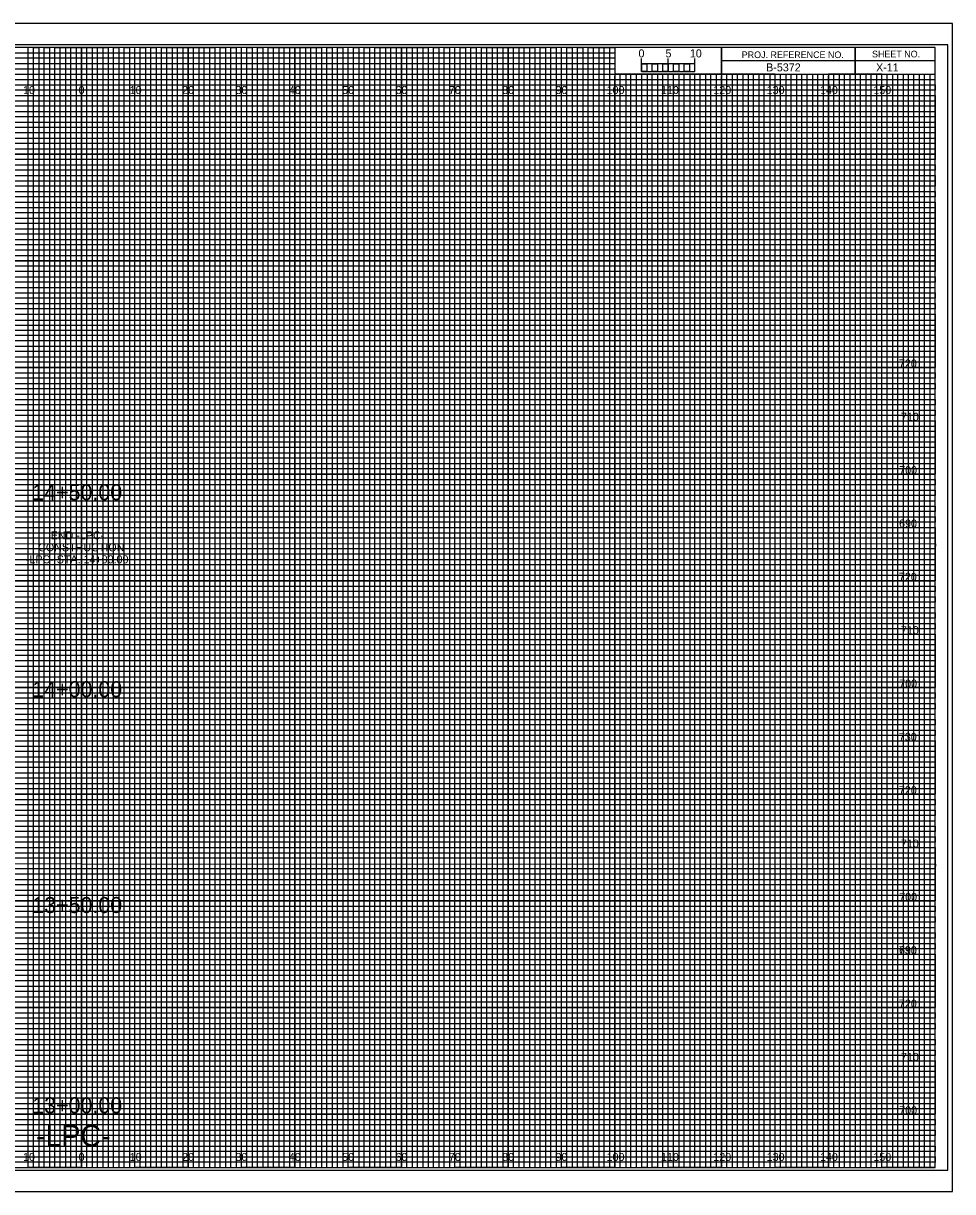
# Model space of a CAD drawing. Extents: x -397 to 323, y -4 to 654.
# Drawn here: x 149.1 to 323.3, y 435.5 to 654.5 of the extents above; entities that cross this region are included whole.
import ezdxf

# ---------------------------------------------------------------- set-up
doc = ezdxf.new("R2010")
doc.units = 0
for name, color, linetype in [('Default', 7, 'Continuous'), ('Exist XS Center Line Elevation Label', 7, 'Continuous'), ('Prop XS Alignment Label', 7, 'Continuous'), ('Prop XS Bar Scale Labels', 7, 'Continuous'), ('Prop XS Elevation Labels', 7, 'Continuous'), ('Prop XS Offset Labels', 7, 'Continuous'), ('Prop XS Project Number', 7, 'Continuous'), ('Prop XS Sheet Number', 7, 'Continuous'), ('Prop XS Station Labels', 7, 'Continuous'), ('Sheet Cross Section CELL', 7, 'Continuous'), ('Sheet Cross Section Grid Major CELL', 7, 'Continuous'), ('Sheet Cross Section Grid Middle CELL', 7, 'Continuous'), ('Sheet Cross Section Grid Minor 1 CELL', 7, 'Continuous'), ('Sheet Cross Section Grid Minor 2 CELL', 7, 'Continuous'), ('Sheet Cross Section Scale CELL', 7, 'Continuous'), ('Sheet Cutting Line CELL', 7, 'Continuous'), ('Sheet DOT Grid CELL', 7, 'Continuous'), ('Sheet Plot Border Inside CELL', 7, 'Continuous'), ('Sheet Plot Border Outside CELL', 7, 'Continuous')]:
    doc.layers.add(name, color=color, linetype=linetype)

msp = doc.modelspace()

# ---------------------------------------------------------------- linework, layer by layer
at = {"layer": 'Default'}
msp.add_lwpolyline([(-13.4, 435.5), (323.3, 435.5), (323.3, 654.5), (-13.4, 654.5)], close=True, dxfattribs=at)
at = {"layer": 'Sheet Cross Section CELL'}
for p, q in [((305, 650), (305, 645)), ((305, 645), (305, 650)), ((280, 647.5), (280, 645)), ((320, 647.49), (280, 647.49)), ((280, 645), (320, 645))]:
    msp.add_line(p, q, dxfattribs=at)
for points in [[(320, 650), (0, 650), (0, 440), (320, 440)], [(280, 650), (260, 650), (260, 645.03), (280, 645.03)], [(320, 650), (280, 650), (280, 645), (320, 645)]]:
    msp.add_lwpolyline(points, close=True, dxfattribs=at)
at = {"layer": 'Sheet Cross Section Grid Major CELL'}
for p, q in [((150, 650), (140, 650)), ((150, 440), (150, 650)), ((170, 650), (160, 650)), ((160, 650), (160, 440)), ((170, 440), (170, 650)), ((190, 650), (180, 650)), ((180, 650), (180, 440)), ((190, 440), (190, 650)), ((210, 650), (200, 650)), ((200, 650), (200, 440)), ((210, 440), (210, 650)), ((230, 650), (220, 650)), ((220, 650), (220, 440)), ((230, 440), (230, 650)), ((250, 650), (240, 650)), ((240, 650), (240, 440)), ((250, 440), (250, 650)), ((260, 650), (260, 440)), ((270, 440), (270, 645)), ((290, 645), (280, 645)), ((280, 645), (280, 440)), ((290, 440), (290, 645)), ((310, 645), (300, 645)), ((300, 645), (300, 440)), ((310, 440), (310, 645)), ((160, 440), (150, 440)), ((180, 440), (170, 440)), ((200, 440), (190, 440)), ((220, 440), (210, 440)), ((240, 440), (230, 440)), ((260, 440), (250, 440)), ((280, 440), (270, 440)), ((300, 440), (290, 440)), ((320, 440), (310, 440)), ((320, 440), (320, 440))]:
    msp.add_line(p, q, dxfattribs=at)
for points in [[(0, 640), (320, 640), (320, 630), (0, 630)], [(0, 620), (320, 620), (320, 610), (0, 610)], [(0, 600), (320, 600), (320, 590), (0, 590)], [(0, 580), (320, 580), (320, 570), (0, 570)], [(0, 560), (320, 560), (320, 550), (0, 550)], [(0, 540), (320, 540), (320, 530), (0, 530)], [(0, 520), (320, 520), (320, 510), (0, 510)], [(0, 500), (320, 500), (320, 490), (0, 490)], [(0, 480), (320, 480), (320, 470), (0, 470)], [(0, 460), (320, 460), (320, 450), (0, 450)]]:
    msp.add_lwpolyline(points, dxfattribs=at)
at = {"layer": 'Sheet Cross Section Grid Middle CELL'}
for points in [[(145, 440), (155, 440), (155, 650), (165, 650), (165, 440), (175, 440), (175, 650), (185, 650), (185, 440), (195, 440), (195, 650), (205, 650), (205, 440), (215, 440), (215, 650), (225, 650), (225, 440), (235, 440), (235, 650), (245, 650), (245, 440), (255, 440), (255, 650), (259.93, 650), (260, 650), (260, 645), (264.99, 645), (264.99, 440), (275, 440), (275, 645), (285, 645), (285, 440), (295, 440), (295, 645), (305, 645), (305, 440), (315, 440), (315, 645)], [(0, 645), (275, 645)], [(0, 625), (320, 625), (320, 635), (0, 635)], [(0, 605), (320, 605), (320, 615), (0, 615)], [(0, 585), (320, 585), (320, 595), (0, 595)], [(0, 565), (320, 565), (320, 575), (0, 575)], [(0, 545), (320, 545), (320, 555), (0, 555)], [(0, 525), (320, 525), (320, 535), (0, 535)], [(0, 505), (320, 505), (320, 515), (0, 515)], [(0, 485), (320, 485), (320, 495), (0, 495)], [(0, 465), (320, 465), (320, 475), (0, 475)], [(0, 445), (320, 445), (320, 455), (0, 455)]]:
    msp.add_lwpolyline(points, dxfattribs=at)
at = {"layer": 'Sheet Cross Section Grid Minor 1 CELL'}
for p, q in [((0, 649), (260, 649)), ((260, 649), (260, 647.98)), ((260, 647.98), (0, 647.98)), ((0, 647), (260, 647)), ((260, 647), (260, 645.89)), ((260, 645.89), (0, 645.89)), ((0, 644), (320, 644))]:
    msp.add_line(p, q, dxfattribs=at)
for points in [[(0, 643), (270, 643), (320, 643), (320, 642), (0, 642)], [(0, 641), (320, 641), (320, 639), (0, 639)], [(0, 638), (320, 638), (320, 637), (0, 636.98)], [(0, 636), (320, 636), (320, 634), (0, 634)], [(0, 633), (320, 633), (320, 632), (0, 632)], [(0, 631), (320, 631), (320, 629), (0, 629)], [(0, 628), (320, 628), (320, 627), (0, 627)], [(0, 626), (320, 626), (320, 624), (0, 624)], [(0, 623), (320, 623), (320, 622), (0, 622)], [(0, 621), (320, 621), (320, 619), (0, 619)], [(0, 618), (320, 618), (320, 617), (0, 617)], [(0, 616), (320, 616), (320, 613.95), (320, 613), (320, 612), (0, 612)], [(0, 614), (320, 614), (320, 613), (0, 613)], [(0, 611), (320, 611), (320, 609), (0, 609.03)], [(0, 609.03), (320, 609), (320, 608), (0, 608)], [(0, 607), (320, 607), (320, 606), (0, 606)], [(0, 604), (320, 604), (320, 603), (0, 603)], [(0, 602), (320, 602), (320, 601), (0, 601)], [(-0.07, 598.89), (320, 598.89), (320, 597.88), (-0.07, 597.88)], [(0, 597), (320, 597), (320, 596), (0, 596)], [(0, 594), (320, 594), (320, 593), (0, 593)], [(0, 592), (320, 592), (320, 591), (0, 591)], [(0, 589), (320, 589), (320, 588), (0, 588)], [(0, 587), (320, 587), (320, 586), (0, 586)], [(0, 584), (320, 584), (320, 583), (0, 583)], [(0, 582), (320, 582), (320, 581), (0, 581)], [(0, 579), (320, 579), (319.99, 577.98), (0, 578)], [(0, 577), (320, 577), (320, 576), (0, 576)], [(0, 574), (320, 574), (320, 573), (0, 573)], [(0, 572), (320, 572), (320, 571), (0, 571)], [(0, 569), (320, 569), (320, 568), (0, 568)], [(0, 567), (320, 567), (320, 566), (0, 566)], [(0, 564), (320, 564), (320, 563), (0, 563)], [(0, 562), (320, 562), (320, 561), (0, 561)], [(0, 559), (320, 559), (320, 558), (0, 558)], [(0, 556.99), (320.07, 556.91), (320, 556), (0, 556)], [(0, 554), (320, 554), (320, 553), (0, 553)], [(0, 552), (320, 552), (320, 551), (0, 551)], [(0, 549), (320, 549), (320, 548), (0, 548)], [(0, 547), (320, 547), (320, 546), (0, 546)], [(0, 544), (320, 544), (320, 543), (0, 543)], [(0, 542), (320, 542), (320, 541), (0, 541)], [(0, 539), (320, 539), (320, 538), (0, 538)], [(0, 537), (320, 537), (320, 536), (0, 536)], [(0, 534), (320, 534), (320, 533), (0, 533)], [(0, 532), (320, 532), (320, 531), (0, 531)], [(0, 529), (320, 529), (320, 528), (0, 528)], [(0, 527), (320, 527), (320, 526), (0, 526)], [(0, 524), (320, 524), (320, 523), (0, 523)], [(0, 522), (320, 522), (320, 521), (0, 521)], [(0, 519), (320, 519), (319.99, 517.98), (0, 518)], [(0, 517), (320, 517), (320, 516), (0, 516)], [(0, 514), (320, 514), (320, 513), (0, 513)], [(0, 512), (320, 512), (320, 511), (0, 511)], [(0, 509), (320, 509), (320, 508), (0, 508)], [(0, 507), (320, 507), (320, 506), (0, 506)], [(0, 504), (320, 504), (320, 503), (0, 503)], [(0, 502), (320, 502), (320, 501), (0, 501)], [(0, 499), (320, 499), (320, 498), (0, 498)], [(0, 496.99), (320.07, 496.91), (320, 496), (0, 496)], [(0, 494), (320, 494), (320, 493), (0, 493)], [(0, 492), (320, 492), (320, 491), (0, 491)], [(0, 489), (320, 489), (320, 488), (0, 488)], [(0, 487), (320, 487), (320, 486), (0, 486)], [(0, 484), (320, 484), (320, 483), (0, 483)], [(0, 482), (320, 482), (320, 481), (0, 481)], [(0, 479), (320, 479), (320, 478), (0, 478)], [(0, 477), (320, 477), (320, 476), (0, 476)], [(0, 474), (320, 474), (320, 473), (0, 473)], [(0, 472), (320, 472), (320, 471), (0, 471)], [(0, 469), (320, 469), (320, 468), (0, 468)], [(0, 467), (320, 467), (320, 466), (0, 466)], [(0, 464), (320, 464), (320, 463), (0, 463)], [(0, 462), (320, 462), (320, 461), (0, 461)], [(0, 459), (320, 459), (320, 458), (0, 458)], [(0, 457), (320, 457), (320, 456), (0, 456)], [(0, 454), (320, 454), (320, 453), (0, 453)], [(0, 452), (320, 452), (320, 451), (0, 451)], [(0, 449), (320, 449), (320, 448), (0, 448)], [(0, 447), (320, 447), (320, 446), (0, 446)], [(0, 444), (320, 444), (320, 443), (0, 443)], [(0, 442), (320, 442), (320, 441), (0, 441)]]:
    msp.add_lwpolyline(points, dxfattribs=at)
at = {"layer": 'Sheet Cross Section Grid Minor 2 CELL'}
for p, q in [((267, 645), (266.01, 645)), ((266.01, 645), (266.01, 440)), ((267, 440), (267, 645)), ((269, 645), (268, 645)), ((268, 645), (268, 440)), ((269, 440), (269, 645)), ((266.01, 440), (265, 440)), ((268, 440), (267, 440))]:
    msp.add_line(p, q, dxfattribs=at)
for points in [[(150, 440), (151, 440), (151, 650), (152, 650), (152, 440)], [(152, 440), (153, 440), (153, 650), (154, 650), (154, 440)], [(155, 440), (156, 440), (156, 650), (157, 650), (157, 440)], [(157, 440), (158, 440), (158, 650), (159, 650), (159, 440)], [(160, 440), (161, 440), (161, 650), (162, 650), (162, 440)], [(162, 440), (163, 440), (163, 650), (164, 650), (164, 440)], [(165, 440), (166, 440), (166, 650), (167, 650), (167, 440)], [(167, 440), (168, 440), (168, 650), (169, 650), (169, 440)], [(170, 440), (171, 440), (171, 650), (172, 650), (172, 440)], [(172, 440), (173, 440), (173, 650), (174, 650), (174, 440)], [(175, 440), (176, 440), (176, 650), (177, 650), (177, 440)], [(177, 440), (178, 440), (178, 650), (179, 650), (179, 440)], [(180, 440), (181, 440), (181, 650), (182, 650), (182, 440)], [(182, 440), (183, 440), (183, 650), (184, 650), (184, 440)], [(185, 440), (186, 440), (186, 650), (187, 650), (187, 440)], [(187, 440), (188, 440), (188, 650), (189, 650), (189, 440)], [(190, 440), (191, 440), (191, 650), (192, 650), (192, 440)], [(192, 440), (193, 440), (193, 650), (194, 650), (194, 440)], [(195, 440), (196, 440), (196, 650), (197, 650), (197, 440)], [(197, 440), (198, 440), (198, 650), (199, 650), (199, 440)], [(200, 440), (201, 440), (201, 650), (202, 650), (202, 440)], [(202, 440), (203, 440), (203, 650), (204, 650), (204, 440)], [(205, 440), (206, 440), (206, 650), (207, 650), (207, 440)], [(207, 440), (208, 440), (208, 650), (209, 650), (209, 440)], [(210, 440), (211, 440), (211, 650), (212, 650), (212, 440)], [(212, 440), (213, 440), (213, 650), (214, 650), (214, 440)], [(215, 440), (216, 440), (216, 650), (217, 650), (217, 440)], [(217, 440), (218, 440), (218, 650), (219, 650), (219, 440)], [(220, 440), (221, 440), (221, 650), (222, 650), (222, 440)], [(222, 440), (223, 440), (223, 650), (224, 650), (224, 440)], [(225, 440), (226, 440), (226, 650), (227, 650), (227, 440)], [(227, 440), (228, 440), (228, 650), (229, 650), (229, 440)], [(230, 440), (231, 440), (231, 650), (232, 650), (232, 440)], [(232, 440), (233, 440), (233, 650), (234, 650), (234, 440)], [(235, 440), (236, 440), (236, 650), (237, 650), (237, 440)], [(237, 440), (238, 440), (238, 650), (239, 650), (239, 440)], [(240, 440), (241, 440), (241, 650), (242, 650), (242, 440)], [(242, 440), (243, 440), (243, 650), (244, 650), (244, 440)], [(245, 440), (246, 440), (246, 650), (247, 650), (247, 440)], [(247, 440), (248, 440), (248, 650), (249, 650), (249, 440)], [(250, 440), (251, 440), (251, 650), (252, 650), (252, 440)], [(252, 440), (253, 440), (253, 650), (254, 650), (254, 440)], [(255, 440), (256, 440), (256, 650), (257, 650), (257, 440)], [(257, 440), (258, 440), (258, 650), (259, 650), (259, 440)], [(260, 440), (261, 440), (261, 645), (262.02, 645), (262.02, 440)], [(262, 440), (263, 440), (263, 645), (263.99, 645), (263.99, 440)], [(270, 440), (270.98, 440), (270.98, 645), (272, 645), (272, 440)], [(272, 440), (273, 440), (273, 645), (274.05, 645), (274.05, 440)], [(275, 440), (276, 440), (276, 645), (277, 645), (277, 440)], [(277, 440), (278, 440), (278, 645), (279, 645), (279, 440)], [(280, 440), (281, 440), (281, 645), (282, 645), (282, 440)], [(282, 440), (283, 440), (283, 645), (284, 645), (284, 440)], [(285, 440), (286, 440), (286, 645), (287, 645), (287, 440)], [(287, 440), (288, 440), (288, 645), (289, 645), (289, 440)], [(290, 440), (291, 440), (291, 645), (292, 645), (292, 440)], [(292, 440), (293, 440), (293, 645), (294, 645), (294, 440)], [(295, 440), (296, 440), (296, 645), (297, 645), (297, 440)], [(297, 440), (298, 440), (298, 645), (299, 645), (299, 440)], [(300, 440), (301, 440), (301, 645), (302, 645), (302, 440)], [(302, 440), (303, 440), (303, 645), (304, 645), (304, 440)], [(305, 440), (306, 440), (306, 645), (307, 645), (307, 440)], [(307, 440), (308, 440), (308, 645), (309, 645), (309, 440)], [(310, 440), (311, 440), (311, 645), (312, 645), (312, 440)], [(312, 440), (313, 440), (313, 645), (314, 645), (314, 440)], [(315, 440), (316, 440), (316, 645), (317, 645), (317, 440)], [(317, 440), (318, 440), (318, 645), (319, 645), (319, 440)]]:
    msp.add_lwpolyline(points, dxfattribs=at)
at = {"layer": 'Sheet Cross Section Scale CELL'}
for p, q in [((265, 645.49), (265, 647.9)), ((265, 646.9), (265, 647.9)), ((270, 645.49), (270, 647.9)), ((275, 645.49), (275, 647.9)), ((275, 646.9), (275, 647.9))]:
    msp.add_line(p, q, dxfattribs=at)
for points in [[(275, 646.9), (265, 646.9), (265, 645.49), (275, 645.49)], [(265, 646.9), (266, 646.9), (266, 645.49), (265, 645.49)], [(267, 646.9), (268, 646.9), (268, 645.49), (267, 645.49)], [(269, 646.9), (270, 646.9), (270, 645.49), (269, 645.49)], [(271, 646.9), (272, 646.9), (272, 645.49), (271, 645.49)], [(273, 646.9), (274, 646.9), (274, 645.49), (273, 645.49)]]:
    msp.add_lwpolyline(points, close=True, dxfattribs=at)
at = {"layer": 'Sheet Cutting Line CELL'}
for p, q in [((323.3, 654.5), (-13.4, 654.5)), ((-13.4, 435.5), (323.3, 435.5))]:
    msp.add_line(p, q, dxfattribs=at)
at = {"layer": 'Sheet DOT Grid CELL'}
for p, q in [((150, 440), (150, 650)), ((160, 440), (160, 650)), ((170, 440), (170, 650)), ((180, 440), (180, 650)), ((190, 440), (190, 650)), ((200, 440), (200, 650)), ((210, 440), (210, 650)), ((220, 440), (220, 650)), ((230, 440), (230, 650)), ((240, 440), (240, 650)), ((250, 440), (250, 650)), ((260, 440), (260, 644.69)), ((270, 440), (270, 644.69)), ((280, 440), (280, 644.69)), ((290, 440), (290, 644.69)), ((300, 440), (300, 644.69)), ((310, 440), (310, 644.69)), ((0, 640), (320, 640)), ((0, 630), (320, 630)), ((0, 620), (320, 620)), ((0, 610), (320, 610)), ((0, 600), (320, 600)), ((0, 590), (320, 590)), ((0, 580), (320, 580)), ((0, 570), (320, 570)), ((0, 560), (320, 560)), ((0, 550), (320, 550)), ((0, 540), (320, 540)), ((0, 530), (320, 530)), ((0, 520), (320, 520)), ((0, 510), (320, 510)), ((0, 500), (320, 500)), ((0, 490), (320, 490)), ((0, 480), (320, 480)), ((0, 470), (320, 470)), ((0, 460), (320, 460)), ((0, 450), (320, 450))]:
    msp.add_line(p, q, dxfattribs=at)
at = {"layer": 'Sheet Plot Border Inside CELL'}
msp.add_lwpolyline([(-10.8, 439.5), (322.4, 439.5), (322.4, 650.5), (-10.8, 650.5)], close=True, dxfattribs=at)
at = {"layer": 'Sheet Plot Border Outside CELL'}
msp.add_lwpolyline([(-13.4, 435.5), (323.3, 435.5), (323.3, 654.5), (-13.4, 654.5)], close=True, dxfattribs=at)

# ---------------------------------------------------------------- texts
at = {"layer": 'Exist XS Center Line Elevation Label'}
for s, p in [('END -LPC-', (154.22, 557.78)), ('CONSTRUCTION', (151.87, 555.53)), ('-LPC- STA. 14+00.00', (149.56, 553.28))]:
    msp.add_text(s, height=1.5, dxfattribs=at).set_placement(p)
at = {"layer": 'Prop XS Alignment Label'}
msp.add_text('-LPC-', height=4, dxfattribs=at).set_placement((151.47, 444))
at = {"layer": 'Prop XS Bar Scale Labels'}
for s, p in [('5', (269.47, 648.12)), ('10', (274.04, 648.12))]:
    msp.add_text(s, height=1.5, dxfattribs=at).set_placement(p)
at = {"layer": 'Prop XS Elevation Labels'}
for s, p in [('720', (313.23, 590)), ('710', (313.61, 580)), ('700', (313.28, 570)), ('690', (313.26, 560)), ('720', (313.23, 550)), ('710', (313.61, 540)), ('700', (313.28, 530)), ('730', (313.22, 520)), ('720', (313.23, 510)), ('710', (313.61, 500)), ('700', (313.28, 490)), ('730', (313.22, 480)), ('690', (313.26, 480)), ('720', (313.23, 470)), ('710', (313.61, 460)), ('700', (313.28, 450))]:
    msp.add_text(s, height=1.5, dxfattribs=at).set_placement(p)
at = {"layer": 'Prop XS Offset Labels'}
for s, p in [('10', (149.04, 641.25)), ('0', (159.45, 641.25)), ('0', (159.45, 641.25)), ('10', (169.04, 641.25)), ('20', (178.86, 641.25)), ('30', (188.86, 641.25)), ('40', (198.86, 641.25)), ('50', (208.86, 641.25)), ('60', (218.86, 641.25)), ('70', (228.86, 641.25)), ('80', (238.86, 641.25)), ('90', (248.86, 641.25)), ('100', (258.44, 641.25)), ('110', (268.62, 641.25)), ('120', (278.44, 641.25)), ('130', (288.44, 641.25)), ('140', (298.44, 641.25)), ('150', (308.44, 641.25)), ('10', (149.04, 441.25)), ('0', (159.45, 441.25)), ('0', (159.45, 441.25)), ('10', (169.04, 441.25)), ('20', (178.86, 441.25)), ('30', (188.86, 441.25)), ('40', (198.86, 441.25)), ('50', (208.86, 441.25)), ('60', (218.86, 441.25)), ('70', (228.86, 441.25)), ('80', (238.86, 441.25)), ('90', (248.86, 441.25)), ('100', (258.44, 441.25)), ('110', (268.62, 441.25)), ('120', (278.44, 441.25)), ('130', (288.44, 441.25)), ('140', (298.44, 441.25)), ('150', (308.44, 441.25))]:
    msp.add_text(s, height=1.5, dxfattribs=at).set_placement(p)
at = {"layer": 'Prop XS Project Number'}
msp.add_text('B-5372', height=1.5, dxfattribs=at).set_placement((288.34, 645.5))
at = {"layer": 'Prop XS Sheet Number'}
msp.add_text('X-11', height=1.5, dxfattribs=at).set_placement((308.95, 645.5))
at = {"layer": 'Prop XS Station Labels'}
for s, p in [('14+50.00', (150.77, 565.11)), ('14+00.00', (150.77, 528.18)), ('13+50.00', (150.77, 487.73)), ('13+00.00', (150.77, 450.19))]:
    msp.add_text(s, height=3, dxfattribs=at).set_placement(p)
at = {"layer": 'Sheet Cross Section CELL'}
for s, p in [('PROJ. REFERENCE NO.', (283.77, 647.99)), ('SHEET NO.', (308.19, 648.12))]:
    msp.add_text(s, height=1.25, dxfattribs=at).set_placement(p)
at = {"layer": 'Sheet Cross Section Scale CELL'}
msp.add_text('0', height=1.5, dxfattribs=at).set_placement((264.41, 648.12))

doc.saveas('drawing.dxf')
